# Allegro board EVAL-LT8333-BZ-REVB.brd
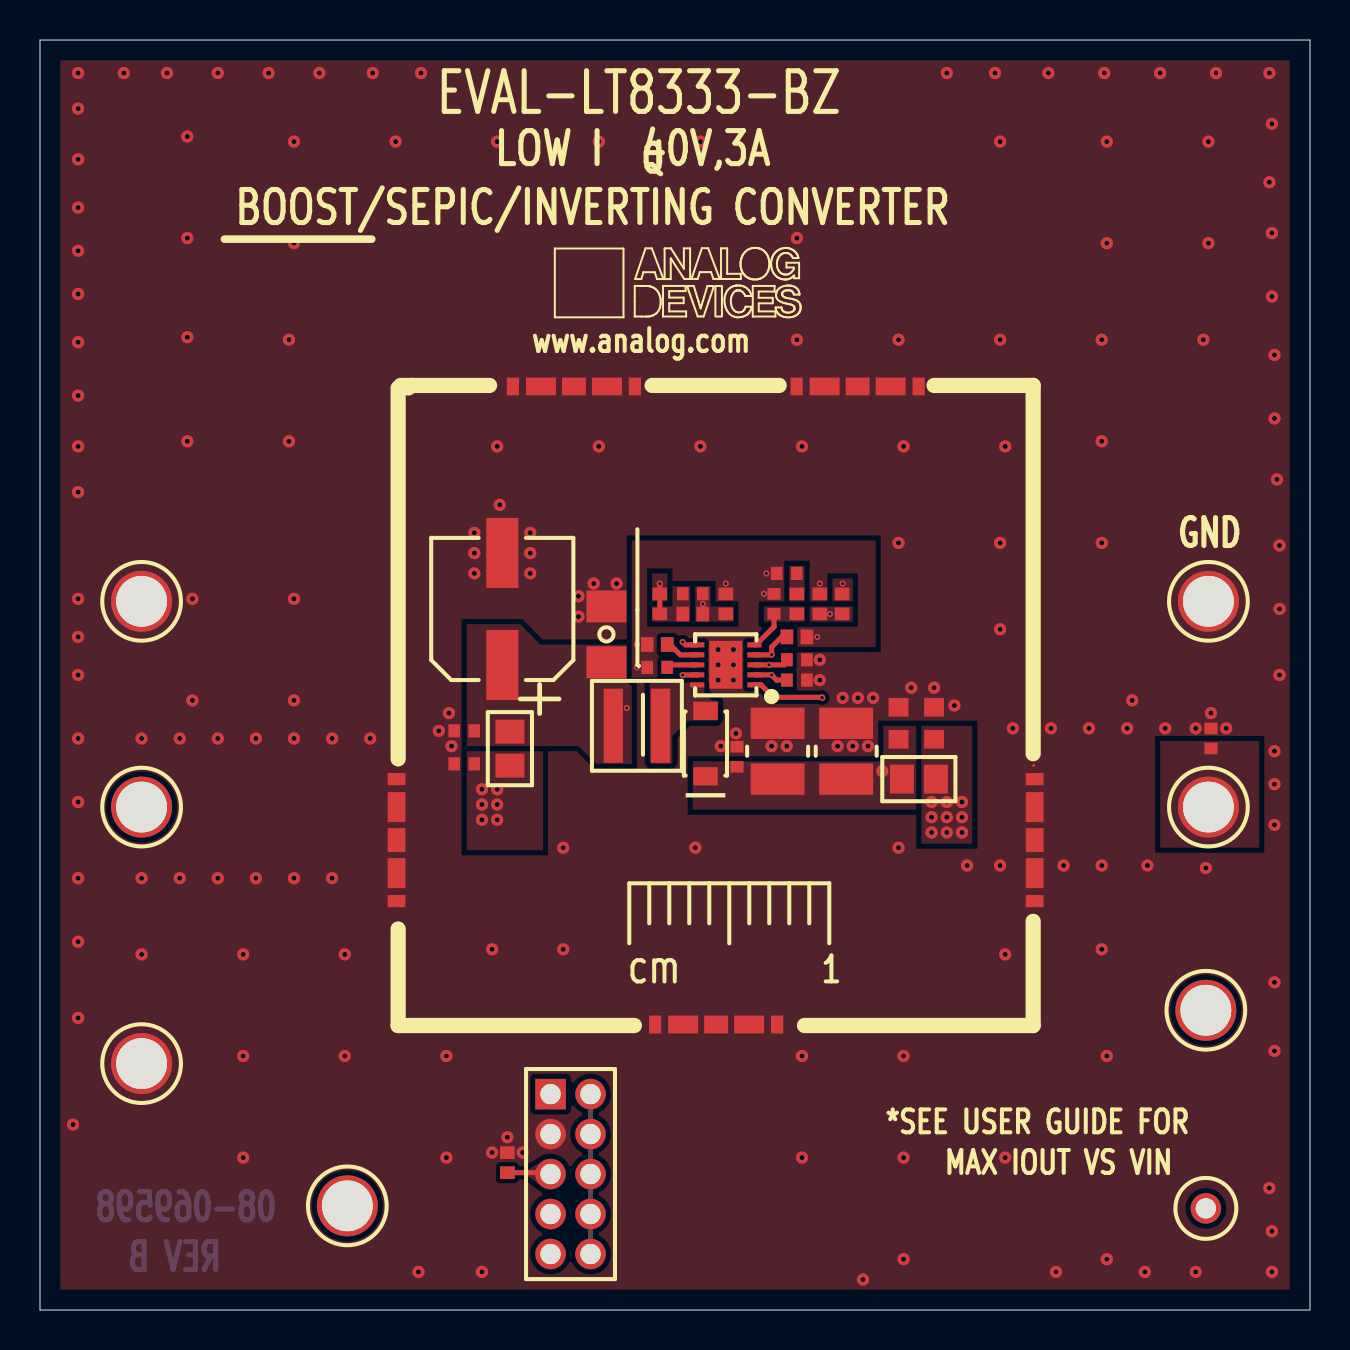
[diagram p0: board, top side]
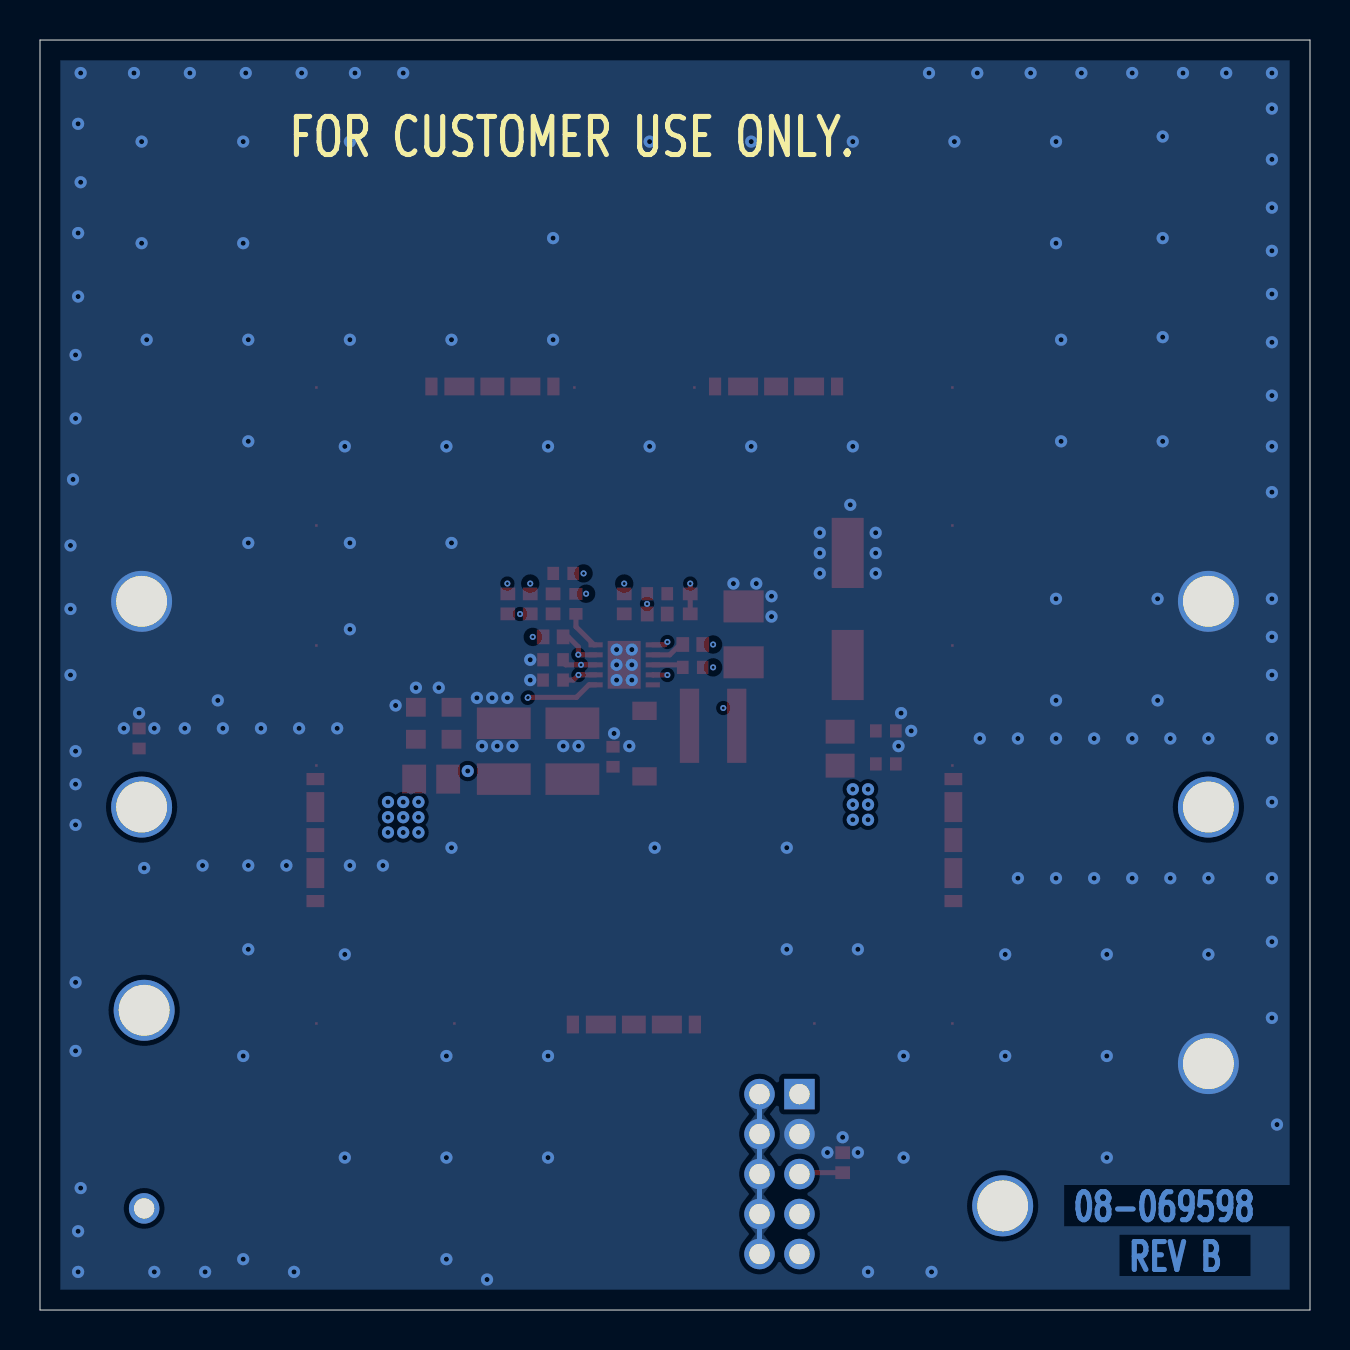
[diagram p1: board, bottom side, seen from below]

Outline 63.5 x 63.5 mm; copper layers: TOP, LAYER_2, LAYER_3, BOTTOM. Coordinates in mm from the lower left corner of the outline.
Outline path: 0,63.5 63.5,63.5 63.5,0 0,0 0,63.5

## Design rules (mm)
constraint set DEFAULT: min track width 0.254

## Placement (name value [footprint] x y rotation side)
C1  10uF  [C1210-2]  40.31 27.94 90 top
C2  10uF  [C1210-2]  36.88 27.94 90 top
C3  1UF  [C0402]  58.55 28.57 270 top
C4  10UF  [C1206H71]  28.32 33.78 90 top
C5  TBD0402  [C0402]  32.64 35.81 0 top
C6  0.1uF  [C0402]  30.86 32.13 180 top
C7  1UF  [C0402]  37.85 32.51 0 top
C8  TBD0402  [C0402]  36.7 35.31 90 top
C9  1NF  [C0402]  37.34 36.83 180 top
C10  0.1UF  [C0402]  37.85 31.5 0 top
C11  1UF  [C0402]  21.21 28.96 0 top
C12  1UF  [C0402]  21.21 27.3 180 top
C13  68UF  [CPLSMSQ260H217_A]  23.11 35.05 90 top
C14  0.1UF  [C0402]  34.85 27.66 90 top
C16  2.2uF  [C0603]  42.93 29.34 90 top
C17  2.2uF  [C0603]  44.7 29.34 90 top
CL1  36900000  [CNWURTH36900000]  33.81 14.27 0 top
CL2  36900000  [CNWURTH36900000]  49.73 23.5 90 top
CL3  36900000  [CNWURTH36900000]  17.83 23.5 270 top
CL4  36900000  [CNWURTH36900000]  26.7 46.18 0 top
CL5  36900000  [CNWURTH36900000]  40.88 46.18 0 top
D1  SS34FA  [SOD123FLH53]  33.27 28.32 90 top
E1  2501-2-00-80-00-00-07-0  [CNMILLMAX2501]  5.08 25.15 0 top
E2  2501-2-00-80-00-00-07-0  [CNMILLMAX2501]  5.08 35.43 0 top
E3  2501-2-00-80-00-00-07-0  [CNMILLMAX2501]  58.29 14.99 180 top
E4  2501-2-00-80-00-00-07-0  [CNMILLMAX2501]  15.37 5.21 180 top
E5  2501-2-00-80-00-00-07-0  [CNMILLMAX2501]  5.08 12.32 180 top
E6  2501-2-00-80-00-00-07-0  [CNMILLMAX2501]  58.42 25.15 0 top
E7  2501-2-00-80-00-00-07-0  [CNMILLMAX2501]  58.42 35.43 0 top
FB1  330 OHM AT 100MEGHZ  [L0805H43]  23.5 28.07 90 top
FB2  600 OHM  [L0805H43]  43.94 26.54 0 top
JP1  TMM-105-01-F-D  [CNHDR2X5H185]  25.53 10.79 270 top
L1  2.2UH  [LSMSQ157H122]  29.84 29.21 0 top
NOREF  -  []  24.2 -29 0 top
NOREF#2  -  []  -234.46 234.55 0 top
NOREF#3  -  []  -316.2 -240 0 top
NOREF#4  -  []  0 0 90 top
NOREF#5  -  []  -17.8 250.8 0 top
NOREF#6  -  []  29.46 21.34 0 top
NOREF#7  -  []  214.63 95.25 0 top
NOREF#8  -  []  -316.2 -240 0 top
NOREF#9  -  []  207.61 158.76 0 top
NOREF#10  -  []  0.6 0.6 0 top
NOREF#11  -  []  92.1 -17.8 270 top
NOREF#12  -  []  -316.2 -240 0 top
NOREF#13  -  []  62.87 62.87 180 top
NOREF#14  -  []  26.5 -18.3 0 top
NOREF#15  -  []  0 63.5 0 top
NOREF#16  -  []  0.64 62.87 270 top
NOREF#17  -  []  -228.98 82.55 0 top
NOREF#18  -  []  -230.75 211.69 0 top
NOREF#19  -  []  -230.7 188.83 0 top
NOREF#20  -  []  62.87 0.76 90 top
R1  1MEG  [R0402]  32.64 34.8 0 top
R2  71.5K  [R0402]  34.29 35.31 90 top
R3  1MEG  [R0402]  40.11 35.31 270 top
R4  549K  [R0402]  38.99 35.31 90 top
R5  20K  [R0402]  30.86 33.27 180 top
R6  43K  [R0402]  37.85 35.31 90 top
R7  0  [R0402]  37.85 33.66 0 top
R8  100K  [R0402]  23.37 7.37 90 top
R9  TBD0402  [R0402]  30.99 35.31 90 top
SH1  36906326S  [M36906326S]  33.78 30.23 0 top
TP1  BLK  [CNKEY5001TP]  58.29 5.08 180 top
U1  LT8333RDD#PBF  [DFN10_3X3_PAD2_38X1_64_PIN11]  34.29 32.26 90 top

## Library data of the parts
C1 C2 = CAP: Tolerance: 10; User Part Number: UPN; alternate symbols: (); part number: CAP_SM-10UF,50V,10,E033329,C1210-2; tolerance: 10
C3 C11 C12 = CAP: User Part Number: UPN; Tolerance: 20; alternate symbols: (C0402L); part number: CAP_SM-1UF,50V,20,E044816,C0402; tolerance: 20
C4 = CAP: Tolerance: 10; User Part Number: UPN; alternate symbols: (C1206H71L); part number: CAP_SM-10UF,50V,10,E045588,C1206H71; tolerance: 10
C5 C8 = CAP: User Part Number: UPN; alternate symbols: (C0402L_ALT,C0402L); part number: CAP_SM-TBD0402,TBD0402,TBD0402,E000381,C0402
C6 = CAP: User Part Number: UPN; Tolerance: 10; alternate symbols: (C0402L); part number: CAP_SM-0.1UF,25V,10,E025708,C0402; tolerance: 10
C7 = CAP: User Part Number: UPN; Tolerance: 10; alternate symbols: (C0402L); part number: CAP_SM-1UF,25V,10,E054542,C0402; tolerance: 10
C9 = CAP: User Part Number: UPN; Tolerance: 10; alternate symbols: (C0402L); part number: CAP_SM-1NF,25V,10,E042764,C0402; tolerance: 10
C10 C14 = CAP: User Part Number: UPN; Tolerance: 10; alternate symbols: (C0402L); part number: CAP_SM-0.1UF,50V,10,E048331,C0402; tolerance: 10
C13 = CAPP: User Part Number: UPN; Tolerance: 20; alternate symbols: (); part number: CAPP_SM-68UF,25V,20,E055340,CPLSMSQ260H217_A; tolerance: 20
C16 C17 = CAP: User Part Number: UPN; Tolerance: 20; alternate symbols: (C0603L); part number: CAP_SM-2.2UF,50V,20,E038303,C0603; tolerance: 20
CL1-CL5 = CN5P: User Part Number: UPN; Tolerance: N/A; alternate symbols: (); part number: CN5P_SM-36900000,E054569,CNWURTH36900000; tolerance: N/A
D1 = DIOSCHOTTKY: User Part Number: UPN; Tolerance: N/A; alternate symbols: (); part number: DIOSCHOTTKY_SM-SS34FA,40V,N/A,E056856,SOD123FLH53; tolerance: N/A
E1-E7 = CNTP1P: User Part Number: UPN; Tolerance: N/A; alternate symbols: (); part number: CNTP1P_TH-2501-2-00-80-00-00-07-0,E031108,CNMILLMAX2501; tolerance: N/A
FB1 = FERRITE: User Part Number: UPN; Tolerance: 25; alternate symbols: (L0805L); part number: FERRITE_SM-330 OHM AT 100MEGHZ,25,E056845,L0805H43; tolerance: 25
FB2 = FERRITE: User Part Number: UPN; Tolerance: 25; alternate symbols: (); part number: FERRITE_SM-600 OHM,25,E048912,L0805H43; tolerance: 25
JP1 = CN10P: Tolerance: N/A; User Part Number: UPN; alternate symbols: (); part number: CN10P_TH-TMM-105-01-F-D,E017872,CNHDR2X5H185; tolerance: N/A
L1 = IND: User Part Number: UPN; Tolerance: 20; alternate symbols: (); part number: IND_SM-2.2UH,20,E054929,LSMSQ157H122; tolerance: 20
NOREF#5 = -: User Part Number: IF SUPPLIED DATA INCLUDES A FILE "READ_ME.2", THEN
R1 R3 = RES: User Part Number: UPN; Tolerance: 1; alternate symbols: (R0402L); part number: RES_SM-1MEG,E041482,1/16W,1,R0402; tolerance: 1
R2 = RES: User Part Number: UPN; Tolerance: 1; alternate symbols: (R0402L); part number: RES_SM-71.5K,E019735,1/16W,1,R0402; tolerance: 1
R4 = RES: User Part Number: UPN; Tolerance: 1; alternate symbols: (R0402L); part number: RES_SM-549K,E026959,1/16W,1,R0402; tolerance: 1
R5 = RES: User Part Number: UPN; Tolerance: 1; alternate symbols: (R0402L,R0402L_ALT); part number: RES_SM-20K,E003791,1/10W,1,R0402; tolerance: 1
R6 = RES: User Part Number: UPN; Tolerance: 1; alternate symbols: (); part number: RES_SM-43K,E056847,1/16W,1,R0402; tolerance: 1
R7 = RES: User Part Number: UPN; Tolerance: JUMPER; alternate symbols: (R0402L,R0402L_ALT); part number: RES_SM-0,E003438,1/10W,JUMPER,R0402; tolerance: JUMPER
R8 = RES: User Part Number: UPN; Tolerance: 1; alternate symbols: (R0402L,R0402L_ALT); part number: RES_SM-100K,E003796,1/10W,1,R0402; tolerance: 1
R9 = RES: User Part Number: UPN; alternate symbols: (R0402L,R0402L_ALT); part number: RES_SM-TBD0402,E004049,TBD0402,TBD0402,R0402
SH1 = MOD_SHLD_20P: User Part Number: UPN; Tolerance: N/A; alternate symbols: (); part number: MOD_SHLD_20P_SM-36906326S,E054570,M36906326S; tolerance: N/A
TP1 = CNTP1P: Tolerance: N/A; User Part Number: UPN; alternate symbols: (); part number: CNTP1P_TH-BLK,E005347,CNKEY5001TP; tolerance: N/A
U1 = ADLT8333: Tolerance: N/A; User Part Number: UPN; alternate symbols: (DFN10_3X3_RLP); part number: ADLT8333_SM-LT8333RDD#PBF,E055341,DFN10_3X3_PAD2_38X1_64_PIN11; tolerance: N/A

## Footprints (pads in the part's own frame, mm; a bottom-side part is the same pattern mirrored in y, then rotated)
C0402
  rect 0.584x0.66 smd: 1(-0.5,0) 2(0.5,0)
C0603
  rect 0.94x0.991 smd: 1(-0.8,0) 2(0.8,0)
C1206H71
  rect 1.6x2.007 smd: 1(-1.397,0) 2(1.397,0)
C1210-2
  rect 1.575x2.692 smd: 1(-1.397,0) 2(1.397,0)
CNHDR2X5H185
  rect 1.524x1.524 hole 1.016: 1(0,0)
  round 1.524 hole 1.016: 2(0,1.999) 3(1.999,0) 4(1.999,1.999) 5(3.998,0) 6(3.998,1.999) 7(5.997,0) 8(5.997,1.999) 9(7.996,0) 10(7.996,1.999)
CNKEY5001TP
  round 1.524 hole 1.016: 1(0,0)
CNMILLMAX2501
  round 3.048 hole 2.54: 1(0,0)
CNWURTH36900000
  rect 0.61x0.889 smd: 1(-3.05,0) 5(3.05,0)
  rect 1.499x0.889 smd: 2(-1.65,0) 4(1.65,0)
  rect 1.194x0.889 smd: 3(0,0)
CPLSMSQ260H217_A
  rect 3.505x1.6 smd: N(2.803,0) P(-2.803,0)
DFN10_3X3_PAD2_38X1_64_PIN11
  rect 0.254x0.711 smd: 1(-1,-1.431) 2(-0.5,-1.431) 3(0,-1.431) 4(0.5,-1.431) 5(1,-1.431) 6(1,1.431) 7(0.5,1.431) 8(0,1.431) 9(-0.5,1.431) 10(-1,1.431)
  rect 2.388x1.651 smd: 11(0,0)
L0805H43
  rect 1.194x1.448 smd: 1(-0.85,0) 2(0.85,0)
LSMSQ157H122
  rect 0.965x3.708 smd: 1(-1.181,0) 2(1.181,0)
M36906326S
  rect 0.127x0.127 smd: 1(-15.9,-15.9) 2(-9,-15.9) 3(-3,-15.9) 4(3,-15.9) 5(9,-15.9) 6(15.9,-15.9) 7(15.9,-9) 8(15.9,-3) 9(15.9,3) 10(15.9,9) 11(15.9,15.9) 12(9,15.9) 13(3,15.9) 14(-3,15.9) 15(-9,15.9) 16(-15.9,15.9) 17(-15.9,9) 18(-15.9,3) 19(-15.9,-3) 20(-15.9,-9)
R0402
  rect 0.635x0.737 smd: 1(-0.5,0) 2(0.5,0)
SOD123FLH53
  rect 0.914x1.219 smd: A(1.638,0) C(-1.638,0)

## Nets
GND_POWER: C1.2(N2) C2.2(N2) C3.1 C4.2(N2) C6.2(N2) C7.2(N2) C8.2(N2) C9.2(N2) C10.2(N2) C11.1 C12.2(N2) C13.N(N2) C14.2(N2) C16.2(N2) C17.2(N2) CL1.1 CL1.2 CL1.3 CL1.4 CL1.5(N5) CL2.1 CL2.2 CL2.3 CL2.4 CL2.5(N5) CL3.1 CL3.2 CL3.3 CL3.4 CL3.5(N5) CL4.1 CL4.2 CL4.3 CL4.4 CL4.5(N5) CL5.1 CL5.2 CL5.3 CL5.4 CL5.5(N5) E2.1(N1) E5.1(N1) E7.1(N1) JP1.3 R2.2(N2) R4.2(N2) R5.2(N2) R7.2(N2) R8.2(N2) SH1.1 SH1.2 SH1.3 SH1.4 SH1.5 SH1.6 SH1.7 SH1.8 SH1.9(SHIELD_9) SH1.10 SH1.11 SH1.12 SH1.13 SH1.14 SH1.15 SH1.16 SH1.17 SH1.18 SH1.19 SH1.20 U1.11
INTVCC: C7.1 JP1.9(N9) U1.3
UNNAMED_3_ADLT8333_I70_BIAS: R7.1 TP1.1(N1) U1.4
UNNAMED_3_ADLT8333_I70_EN: E3.1(N1) R3.2(N2) R4.1 U1.1
UNNAMED_3_ADLT8333_I70_FBX: C5.2(N2) R1.2(N2) R2.1 U1.6
UNNAMED_3_ADLT8333_I70_RT: R5.1 U1.7
UNNAMED_3_ADLT8333_I70_SS: C6.1 U1.8
UNNAMED_3_ADLT8333_I70_SW: D1.A(P) L1.2(N2) U1.10
UNNAMED_3_ADLT8333_I70_SYNC: JP1.2 JP1.4 JP1.6 JP1.8 JP1.10 U1.9
UNNAMED_3_ADLT8333_I70_VC: C8.1 R6.1 U1.5
UNNAMED_3_ADLT8333_I70_VIN: C4.1 C10.1 C11.2(N2) C13.P FB1.2(N2) L1.1 R3.1 U1.2(VIN)
UNNAMED_3_CAP_I27_N1: C9.1 R6.2(N2)
UNNAMED_3_CAP_I64_N1: C3.2(N2) C17.1 E6.1(N1) FB2.2(N2)
UNNAMED_3_CAP_I69_N1: C12.1 E1.1(N1) FB1.1
UNNAMED_3_CN10P_I39_N1: E4.1(N1) JP1.1
UNNAMED_3_CN10P_I39_N5: JP1.5 R8.1
VOUT: C1.1 C2.1 C5.1 C14.1 C16.1 D1.C FB2.1 R1.1 R9.1 R9.2(N2)

Pads without a net: JP1 7

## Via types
v1: diameter 0.61, hole 0.254, TOP to BOTTOM, 200 vias
v2: diameter 0.305, hole 0.152, TOP to BOTTOM, 19 vias

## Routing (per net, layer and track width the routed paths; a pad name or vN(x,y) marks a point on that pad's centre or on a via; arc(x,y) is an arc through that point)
GND_POWER: length 0
  LAYER_2 w0.254: 55.6,18.68 55.63,18.71
  vias: v1(1.65,9.27) v1(1.91,61.85) v1(1.91,60.07) v1(1.91,57.53) v1(1.91,55.12) v1(1.91,52.96) v1(1.91,50.8) v1(1.91,48.39) v1(1.91,45.72) v1(1.91,43.18) v1(1.91,40.89) v1(1.91,35.56) v1(1.91,33.66) v1(1.91,31.75) v1(1.91,28.57) v1(1.91,25.4) v1(1.91,21.59) v1(1.91,18.41) v1(1.91,14.61) v1(4.19,61.85) v1(5.08,28.57) v1(5.08,21.59) v1(5.08,17.78) v1(6.35,61.85) v1(6.99,28.57) v1(6.99,21.59) v1(7.37,58.67) v1(7.37,53.59) v1(7.37,48.64) v1(7.37,43.43) v1(7.62,35.56) v1(7.62,30.48) v1(8.89,61.85) v1(8.89,28.57) v1(8.89,21.59) v1(10.16,17.78) v1(10.16,12.7) v1(10.16,7.62) v1(10.79,28.57) v1(10.79,21.59) v1(11.43,61.85) v1(12.45,48.51) v1(12.45,43.43) v1(12.7,58.42) v1(12.7,53.34) v1(12.7,35.56) v1(12.7,30.48) v1(12.7,28.57) v1(12.7,21.59) v1(13.97,61.85) v1(14.61,28.57) v1(14.61,21.59) v1(15.24,17.78) v1(15.24,12.7) v1(16.51,28.57) v1(16.64,61.85) v1(17.78,58.42) v1(18.92,1.91) v1(19.05,61.85) v1(19.94,28.96) v1(20.32,12.7) v1(20.32,7.62) v1(20.45,29.84) v1(20.57,28.19) v1(21.72,38.86) v1(21.72,37.85) v1(21.72,36.83) v1(22.1,1.91) v1(22.61,18.03) v1(22.61,7.87) v1(22.86,58.42) v1(22.86,43.18) v1(22.99,40.26) v1(23.37,8.64) v1(24.13,7.87) v1(24.51,38.86) v1(24.51,37.85) v1(24.51,36.83) v1(26.16,23.11) v1(26.16,18.03) v1(26.92,35.69) v1(26.92,34.67) v1(27.69,36.32) v1(27.94,58.42) v1(27.94,43.18) v1(28.83,36.32) v1(32.77,23.11) v1(33.02,58.42) v1(33.02,43.18) v1(33.91,33.02) v1(33.91,32.26) v1(33.91,31.5) v1(34.04,28.19) v1(34.67,33.02) v1(34.67,32.26) v1(34.67,31.5) v1(34.8,28.83) v1(36.58,28.19) v1(37.34,28.19) v1(37.85,53.59) v1(37.85,48.51) v1(38.1,43.18) v1(38.1,12.7) v1(38.1,7.62) v1(38.99,32.51) v1(38.99,31.5) v1(39.88,28.19) v1(40.13,30.61) v1(40.64,28.19) v1(40.89,30.61) v1(41.15,1.52) v1(41.4,28.19) v1(41.66,30.61) v1(42.93,48.51) v1(42.93,38.35) v1(42.93,23.11) v1(43.18,43.18) v1(43.18,12.7) v1(43.18,7.62) v1(43.18,2.54) v1(43.56,31.11) v1(44.7,31.11) v1(45.34,61.85) v1(45.72,30.23) v1(46.35,22.23) v1(47.75,61.85) v1(48.01,58.42) v1(48.01,48.51) v1(48.01,38.35) v1(48.01,34.04) v1(48.01,22.23) v1(48.26,43.18) v1(48.26,17.78) v1(48.26,7.62) v1(48.64,29.08) v1(50.42,61.85) v1(50.55,29.08) v1(50.8,1.91) v1(51.18,22.23) v1(52.45,29.08) v1(53.09,48.51) v1(53.09,43.43) v1(53.09,38.35) v1(53.09,22.23) v1(53.09,18.03) v1(53.21,61.85) v1(53.34,58.42) v1(53.34,53.34) v1(53.34,12.7) v1(53.34,2.54) v1(54.36,29.08) v1(54.61,30.48) v1(55.24,1.91) v1(55.37,22.23) v1(56.01,61.85) v1(56.26,29.08) v1(57.78,29.08) v1(57.78,1.91) v1(58.17,48.51) v1(58.29,22.1) v1(58.42,58.42) v1(58.42,53.34) v1(58.55,29.84) v1(58.8,61.85) v1(59.31,29.08) v1(61.47,61.85) v1(61.47,56.39) v1(61.47,6.1) v1(61.59,59.31) v1(61.59,53.85) v1(61.59,50.67) v1(61.59,3.94) v1(61.59,1.91) v1(61.72,47.75) v1(61.72,44.58) v1(61.72,27.94) v1(61.72,26.29) v1(61.72,24.26) v1(61.72,16.38) v1(61.72,12.95) v1(61.85,41.53) v1(61.98,38.23) v1(61.98,35.05) v1(61.98,31.75) v2(29.84,33.27) v2(29.84,32.13) v2(34.29,36.32) v2(36.2,35.81) v2(36.32,36.83) v2(38.86,33.66) v2(38.99,36.32)
INTVCC: length 44.2
  TOP w0.254: C7.1 37.34,32.5 37.34,32.38 37.21,32.26 v2(36.45,32.26) U1.3
  LAYER_3 w0.254: v2(36.45,32.26) 36.96,32.26 37.21,32 37.21,30.99 35.69,29.46 35.69,2.79 34.49,1.6 25.77,1.6 25.52,1.85 25.52,2.79 JP1.9
UNNAMED_3_ADLT8333_I70_BIAS: length 45.4
  TOP w0.254: R7.1 37.08,33.66 36.58,33.15 v2(36.58,32.77) 36.58,32.76 U1.4
  LAYER_3 w0.254: v2(36.58,32.77) 37.21,32.77 38.23,31.75 38.23,14.61 47.75,5.08 TP1.1
UNNAMED_3_ADLT8333_I70_EN: length 39
  TOP w0.254: U1.1 36.05,31.26 36.68,30.63 v2(39.09,30.63)
  LAYER_3 w0.254: E3.1 46.1,14.99 39.12,21.97 v2(39.12,30.61) 39.88,31.37 39.88,34.42 v2(39.5,34.8)
UNNAMED_3_ADLT8333_I70_FBX: length 3.4
  TOP w0.254: U1.6 32.27,33.26 v2(32.13,33.4)
  LAYER_3 w0.254: v2(32.13,33.4) 32.64,33.4 33.15,33.91 v2(33.15,35.31)
UNNAMED_3_ADLT8333_I70_RT: length 1.7
  TOP w0.254: R5.1 31.5,33.27 32.01,32.76 U1.7
UNNAMED_3_ADLT8333_I70_SS: length 1.6
  TOP w0.254: U1.8 31.5,32.26 31.37,32.13 C6.1
UNNAMED_3_ADLT8333_I70_SYNC: length 33.2
  TOP w0.254: U1.9 32.85,31.75 v2(32.13,31.75)
  LAYER_3 w0.254: JP1.2 27.43,10.89 27.43,29.59 29.08,31.24 31.62,31.24 v2(32.13,31.75)
  BOTTOM w0.254: JP1.2 JP1.4 JP1.6 JP1.8 JP1.10
UNNAMED_3_ADLT8333_I70_VC: length 2
  TOP w0.254: C8.1 36.7,34.16 35.8,33.26 U1.5
UNNAMED_3_ADLT8333_I70_VIN: length 18.1
  TOP w0.254: C10.1 36.83,31.5 v2(36.58,31.75) 36.57,31.76 U1.2
  LAYER_3 w0.254: 35.56,31.75 35.56,30.99 34.67,30.1 v2(29.34,30.1) ; 35.56,31.75 35.56,33.65 38.77,36.86 39.6,36.86 v2(40.13,36.32) ; 35.56,31.75 v2(36.58,31.75)
UNNAMED_3_CAP_I64_N1:
  vias: v1(44.58,25.4) v1(44.58,24.64) v1(44.58,23.88) v1(45.34,25.4) v1(45.34,24.64) v1(45.34,23.88) v1(46.1,25.4) v1(46.1,24.64) v1(46.1,23.88)
UNNAMED_3_CAP_I69_N1:
  vias: v1(22.1,26.04) v1(22.1,25.27) v1(22.1,24.51) v1(22.86,26.04) v1(22.86,25.27) v1(22.86,24.51)
UNNAMED_3_CN10P_I39_N1: length 13.1
  LAYER_3 w0.254: E4.1 15.37,6.22 19.94,10.79 JP1.1
UNNAMED_3_CN10P_I39_N5: length 2.2
  TOP w0.254: JP1.5 25.46,6.87 R8.1
VOUT: length 23.8
  TOP w0.254: R9.1 R9.2 v2(30.99,36.32)
  LAYER_3 w0.254: v1(42.11,26.95) 42.55,27.38 42.55,35.56 40.01,38.1 32.51,38.1 30.99,36.58 v2(30.99,36.32)

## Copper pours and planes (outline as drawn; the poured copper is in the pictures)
GND_POWER on TOP: 1.02,62.48 62.48,62.48 62.48,1.02 1.02,1.02 ; 2 cut-outs
GND_POWER on BOTTOM: 1.02,62.48 62.48,62.48 62.48,1.02 1.02,1.02 ; 7 cut-outs
GND_POWER on LAYER_2: 1.02,62.48 62.48,62.48 62.48,1.02 1.02,1.02 ; 1 cut-out
GND_POWER on LAYER_3: 1.02,62.48 62.48,62.48 62.48,1.02 1.02,1.02 ; 7 cut-outs
UNNAMED_3_ADLT8333_I70_EN on TOP: 38.48,35.18 38.48,34.42 40.64,34.42 40.64,35.18
UNNAMED_3_ADLT8333_I70_FBX on TOP: 32.77,36.2 32.77,34.42 34.67,34.42 34.67,35.18 33.53,35.18 33.53,36.2
UNNAMED_3_ADLT8333_I70_SW on TOP: 33.1,31.37 33.19,31.33 33.22,31.24 33.22,30.85 33.6,30.48 33.78,30.48 33.87,30.44 33.91,30.35 33.91,29.59 33.87,29.5 33.78,29.46 32.38,29.46 31.62,28.7 31.62,27.43 31.59,27.34 31.5,27.3 30.61,27.3 30.52,27.34 30.48,27.43 30.48,31.24 30.52,31.33 30.61,31.37
UNNAMED_3_ADLT8333_I70_VC on TOP: 36.2,35.18 36.2,34.42 38.23,34.42 38.23,35.18
UNNAMED_3_ADLT8333_I70_VIN on TOP: 29.34,33.27 29.34,31.42 29.59,31.17 29.59,27.3 27.81,27.3 26.92,28.19 21.34,28.19 21.34,34.29 24,34.29 25.02,33.27
UNNAMED_3_ADLT8333_I70_VIN on TOP: 39.62,36.58 39.62,35.43 40.64,35.43 40.64,36.58
UNNAMED_3_CAP_I27_N1 on TOP: 37.47,37.21 37.47,35.43 38.23,35.43 38.23,37.21
UNNAMED_3_CAP_I64_N1 on TOP: 56.01,28.45 56.01,23.11 60.96,23.11 60.96,28.45
UNNAMED_3_CAP_I64_N1 on TOP: 44.07,29.21 44.07,23.32 46.61,23.32 46.61,29.21
UNNAMED_3_CAP_I64_N1 on LAYER_3: 44.07,23.11 60.96,23.11 60.96,28.45 44.07,28.45
UNNAMED_3_CAP_I69_N1 on TOP: 21.34,27.94 21.34,22.99 25.15,22.99 25.15,27.94
UNNAMED_3_CAP_I69_N1 on LAYER_3: 2.67,27.3 2.67,22.73 23.62,22.73 23.62,27.3
VOUT on TOP: 31.37,35.43 31.37,36.83 30.61,36.83 30.61,35.43
VOUT on TOP: 30.61,35.18 30.61,34.42 32.51,34.42 32.51,36.2 31.62,36.2 31.62,35.18
VOUT on TOP: 32.64,27.43 32.64,25.02 43.81,25.02 43.81,29.21 42.16,29.21 42.16,27.43

Small or netless copper shapes (teardrops, artwork), in the pictures only: 1 on TOP, 8 on BOTTOM, 8 on LAYER_3

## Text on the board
BOTTOM: REV B | 08-069598
Board Geometry/Soldermask Bottom: 06
Ref Des/Silkscreen Bottom: FOR CUSTOMER USE ONLY. | 05
User.Comments: INDICATE DIRECTION OF TERMINALS AND START LEAD. | FOOTPRINT | PART | 5.    INSTALL INDUCTOR L1 AS SHOWN BELOW. | 4.    INSTALL TURRETS AS SHOWN BELOW.
TOP: 01
Board Geometry/Soldermask Top: 04
Ref Des/Silkscreen Top: www.analog.com | *SEE USER GUIDE FOR | MAX IOUT VS VIN | Q | BOOST/SEPIC/INVERTING CONVERTER | LOW I  40V,3A | EVAL-LT8333-BZ | 01
LAYER_2: LAYER 2   GND | 07
LAYER_3: LAYER 3   GND/SIGNAL | 08
ROOT_NUMBER: EVAL-LT8333-BZ | ANALOG DEVICES  DATE: 3-10-2022
PAGE_OUTLINE: EVAL-LT8333-BZ | Q | A | B | ECR-107459 | 11MAR2022 | INVERTING CONVERTER
USER_PART_NUM_TOP: EXTERNAL LAYERS 2 OZ. COPPER, OVERPLATE TO 1.5 OZ.
User.9: 13
User.10: 14
User.13: ASSY1 | ANALOG DEVICES  DATE: 8-5-2021
User.15: PER IPC-4552 LATEST REVISION | ENIG (Electroless Nickel/Immersion Gold) | ~3.5 MIL | LAYER 2 | LAYER 3 | PLUGGED AND COVERED WIITH SOLDMASK.
User.16: PRIMARY GOLD MASK | SECONDARY GOLD MASK | 0.XXX" +/-10% | PRIMARY SILKSCREEN | PRIMARY SOLDER MASK | PRIMARY SIDE    (LAYER 1) | SECONDARY SIDE  (LAYER 2) | SECONDARY SOLDER MASK | SECONDARY SILKSCREEN | NOMINAL | FINISHED | THICKNESS | CHARACTERISTIC IMPEDANCE = 50 OHMS +/- 5% | ARTWORK LINE WIDTH FOR | IMPEDANCE CONTROLLED LINES = 0.xxx" | 2 LAYER STACKUP
User.25: P10
User.27: EVAL-LT7153SP-AZ
User.45: FIGURE | FINISHED_SIZE | 6.0 | 10.0 | 40.0 | 100.0 | DRILL CHART: TOP to BOTTOM | ALL UNITS ARE IN MILS | TOLERANCE_DRILL | +3.0/-1.0 | +0.0/-0.0 | PLATED | QTY | 18 | 200 | 11 | 7
